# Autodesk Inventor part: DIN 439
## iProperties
SaveDate: 2002-10-24
SaveTime: 14:43
TotalMass: 0.0 kg
TotalVolume: 0.0 mm^3
Author: Cor de Vlaming
Shininess: 64.0
Angle Display Precision: 2
Document Length Units: 11269
Document Angle Units: 11283
Document Time Units: 11279
Document Mass Units: 11290
Document Length Units Precision: 3
Document Angle Units Precision: 2
Compacted: True
PropertySet Name: _Private Model Information
Created: 2002-09
Part Number: DIN 439
Cost Center: 0.0 kg
Material: Steel, Mild
Description: Moer volgens DIN 439 / ISO 4035
Document SubType Name: Modeling
Designer: Cor de Vlaming
Authority: 0.0 mm^3
Control State: 0
Master: False
Checked Out: False
PropertySet Name: Design Tracking Control
Density: 0.0
Volumn: 0.0
Area: 0.0
PropertySet Name: Model Information
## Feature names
1. Extrusion1
2. Revolution1
3. Mirror1
4. Chamfer1
5. Extrusion2
